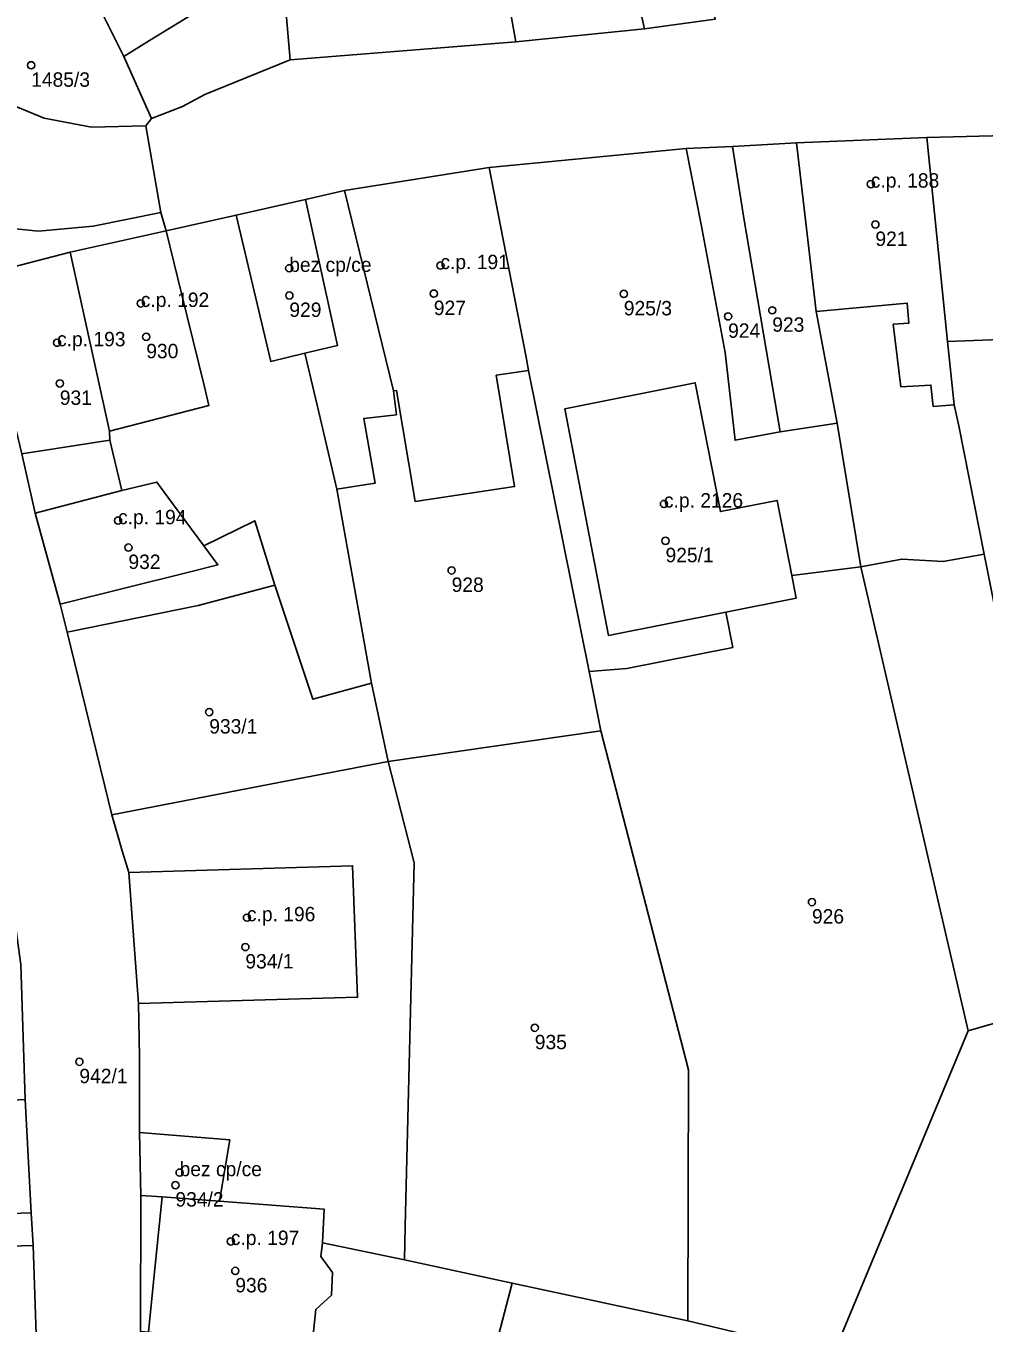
# Model space of a CAD drawing. Extents: x -878211 to -870363, y -1058464 to -1052522.
# Drawn here: x -874825.1 to -874758.5, y -1056399.5 to -1056309.4 of the extents above; entities that cross this region are included whole.
import ezdxf

# ---------------------------------------------------------------- set-up
doc = ezdxf.new("R2010")
doc.units = 0
for name, color, linetype in [('Vrstva 50', 7, 'Continuous'), ('Vrstva 51', 7, 'Continuous'), ('Vrstva 52', 7, 'Continuous')]:
    doc.layers.add(name, color=color, linetype=linetype)

msp = doc.modelspace()

# ---------------------------------------------------------------- linework, layer by layer
at = {"layer": 'Vrstva 50'}
for centre in [(-874824.76, -1056312.13994), (-874766.39, -1056320.38994), (-874766.07, -1056323.19994), (-874796.31, -1056326.04994), (-874806.82, -1056326.23994), (-874817.14, -1056328.67994), (-874806.81, -1056328.12994), (-874796.77, -1056327.99994), (-874783.56, -1056328.01994), (-874776.31, -1056329.57994), (-874773.24, -1056329.15994), (-874822.96, -1056331.40994), (-874816.76, -1056330.99994), (-874822.77, -1056334.23994), (-874780.77, -1056342.60994), (-874818.72, -1056343.76994), (-874818, -1056345.63994), (-874780.66, -1056345.16994), (-874795.53, -1056347.22994), (-874812.38, -1056357.06994), (-874770.48, -1056370.26994), (-874809.76, -1056371.34994), (-874809.87, -1056373.38994), (-874789.75, -1056378.99994), (-874821.41, -1056381.35994), (-874814.44, -1056389.05994), (-874814.73, -1056389.92994), (-874810.88, -1056393.83994), (-874810.57, -1056395.88994)]:
    msp.add_circle(centre, 0.25, dxfattribs=at)
at = {"layer": 'Vrstva 51'}
for points in [[(-874810.41, -1056299.08), (-874807.36, -1056304.78), (-874806.75, -1056311.76), (-874791.06, -1056310.51), (-874792.59, -1056302.01), (-874797.4, -1056303.06), (-874798.34, -1056300.54), (-874798.56, -1056299.76), (-874803.04, -1056301.63), (-874806.58, -1056293.34), (-874807.36, -1056291.06), (-874799.65, -1056288.2), (-874799.18, -1056288.03), (-874800.65, -1056284.47), (-874802.95, -1056281.49), (-874812.35, -1056267.76), (-874825.07, -1056277.66), (-874817.87, -1056288.24), (-874815.27, -1056292.06)], [(-874782.12, -1056309.61), (-874777.22, -1056308.94), (-874777.94, -1056303.47), (-874774.36, -1056303.02), (-874774.94, -1056298.49), (-874775.56, -1056294.88), (-874776.96, -1056286.51), (-874783.86, -1056275.07), (-874788.26, -1056278.25), (-874786.97, -1056279.79), (-874784.95, -1056283.66), (-874785.11, -1056283.85), (-874790.97, -1056286.39), (-874787.35, -1056293.96), (-874784.26, -1056300.23)], [(-874821.24, -1056305.68), (-874820.95, -1056305.48), (-874821.05, -1056305.31), (-874824.38, -1056307.31), (-874825.52, -1056305.39), (-874829.14, -1056307.57), (-874832.24, -1056302.43), (-874825.01, -1056298.2), (-874829.97, -1056300.5), (-874833.03, -1056296.06), (-874834.18, -1056296.79), (-874832.6, -1056300.12), (-874836.12, -1056302.52), (-874835.92, -1056303.06), (-874834.95, -1056305.06), (-874836.72, -1056305.96), (-874834.67, -1056309.32), (-874832.56, -1056311.43), (-874829.27, -1056313.6), (-874823.85, -1056315.82), (-874820.56, -1056316.43), (-874816.79, -1056316.35), (-874816.4, -1056315.83), (-874818.31, -1056311.52)], [(-874810.41, -1056299.08), (-874820.95, -1056305.48), (-874821.24, -1056305.68), (-874818.31, -1056311.52), (-874816.4, -1056315.83), (-874814.25, -1056315), (-874812.69, -1056314.16), (-874806.75, -1056311.76), (-874807.36, -1056304.78)], [(-874791.06, -1056310.51), (-874782.12, -1056309.61), (-874784.26, -1056300.23), (-874792.59, -1056302.01)], [(-874757.27, -1056352.27), (-874748.07, -1056351.04), (-874748.8, -1056346.87), (-874750.14, -1056339.33), (-874751.05, -1056334.17), (-874751.31, -1056330.95), (-874751.33, -1056330.7), (-874751.64, -1056326.89), (-874752.45, -1056316.91), (-874762.49, -1056317.15), (-874761.05, -1056331.33), (-874760.6, -1056335.72), (-874760.27, -1056337.19), (-874758.52, -1056346.1)], [(-874775.83, -1056338.18), (-874772.68, -1056337.6), (-874775.22, -1056322.75), (-874776, -1056317.78), (-874779.23, -1056317.93), (-874778.18, -1056323.19), (-874776.51, -1056332.1)], [(-874771.55, -1056317.53), (-874776, -1056317.78), (-874775.22, -1056322.75), (-874772.68, -1056337.6), (-874768.72, -1056336.99), (-874770.18, -1056329.24), (-874770.97, -1056322.47)], [(-874768.72, -1056336.99), (-874767.09, -1056346.97), (-874764.24, -1056346.44), (-874761.36, -1056346.61), (-874758.52, -1056346.1), (-874760.27, -1056337.19), (-874760.6, -1056335.72), (-874761.05, -1056331.33), (-874762.49, -1056317.15), (-874771.55, -1056317.53), (-874770.97, -1056322.47), (-874770.18, -1056329.24)], [(-874767.09, -1056346.97), (-874768.72, -1056336.99), (-874772.68, -1056337.6), (-874775.83, -1056338.18), (-874776.51, -1056332.1), (-874778.18, -1056323.19), (-874779.23, -1056317.93), (-874792.93, -1056319.24), (-874792.14, -1056323.29), (-874790.36, -1056332.41), (-874790.18, -1056333.33), (-874785.98, -1056354.25), (-874783.34, -1056354.04), (-874775.99, -1056352.58), (-874776.47, -1056350.13), (-874784.62, -1056351.75), (-874787.65, -1056336), (-874778.59, -1056334.19), (-874776.84, -1056343.14), (-874772.91, -1056342.37), (-874771.88, -1056347.58)], [(-874799.37, -1056334.73), (-874798.07, -1056342.44), (-874791.15, -1056341.41), (-874792.43, -1056333.67), (-874790.18, -1056333.33), (-874790.36, -1056332.41), (-874792.14, -1056323.29), (-874792.93, -1056319.24), (-874802.97, -1056320.84), (-874805.69, -1056321.47), (-874803.46, -1056331.6), (-874805.73, -1056332.14), (-874804.67, -1056336.64), (-874803.5, -1056341.58), (-874800.84, -1056341.16), (-874801.64, -1056336.67), (-874799.37, -1056336.41), (-874799.57, -1056334.76)], [(-874805.73, -1056332.14), (-874803.46, -1056331.6), (-874805.69, -1056321.47), (-874810.52, -1056322.54), (-874808.11, -1056332.71)], [(-874805.73, -1056332.14), (-874808.11, -1056332.71), (-874810.52, -1056322.54), (-874815.38, -1056323.63), (-874822.04, -1056325.11), (-874819.32, -1056337.55), (-874819.29, -1056338.18), (-874818.46, -1056341.67), (-874816.02, -1056341.09), (-874815.25, -1056342.14), (-874812.76, -1056345.51), (-874809.22, -1056343.78), (-874807.81, -1056348.25), (-874805.17, -1056356.18), (-874801.09, -1056355.05), (-874803.5, -1056341.58), (-874804.67, -1056336.64)], [(-874818.46, -1056341.67), (-874819.29, -1056338.18), (-874819.32, -1056337.55), (-874822.04, -1056325.11), (-874828.39, -1056326.76), (-874825.4, -1056339.14), (-874824.48, -1056343.25)], [(-874785.16, -1056358.37), (-874785.98, -1056354.25), (-874790.18, -1056333.33), (-874792.43, -1056333.67), (-874791.15, -1056341.41), (-874798.07, -1056342.44), (-874799.37, -1056334.73), (-874799.57, -1056334.76), (-874799.37, -1056336.41), (-874801.64, -1056336.67), (-874800.84, -1056341.16), (-874803.5, -1056341.58), (-874801.09, -1056355.05), (-874799.95, -1056360.5)], [(-874771.88, -1056347.58), (-874772.91, -1056342.37), (-874776.84, -1056343.14), (-874778.59, -1056334.19), (-874787.65, -1056336), (-874784.62, -1056351.75), (-874776.47, -1056350.13), (-874771.57, -1056349.15)], [(-874813.16, -1056349.67), (-874807.81, -1056348.25), (-874809.22, -1056343.78), (-874812.76, -1056345.51), (-874815.25, -1056342.14), (-874816.02, -1056341.09), (-874818.46, -1056341.67), (-874824.48, -1056343.25), (-874822.74, -1056349.57), (-874822.26, -1056351.51)], [(-874759.61, -1056379.22), (-874752.26, -1056377.07), (-874757.27, -1056352.27), (-874758.52, -1056346.1), (-874761.36, -1056346.61), (-874764.24, -1056346.44), (-874767.09, -1056346.97)], [(-874771.88, -1056347.58), (-874771.57, -1056349.15), (-874776.47, -1056350.13), (-874775.99, -1056352.58), (-874783.34, -1056354.04), (-874785.98, -1056354.25), (-874785.16, -1056358.37), (-874779.06, -1056381.92), (-874779.1, -1056399.35), (-874769.04, -1056401.77), (-874759.61, -1056379.22), (-874767.09, -1056346.97)], [(-874807.42, -1056361.94), (-874799.95, -1056360.5), (-874801.09, -1056355.05), (-874805.17, -1056356.18), (-874807.81, -1056348.25), (-874813.16, -1056349.67), (-874822.26, -1056351.51), (-874819.16, -1056364.21)], [(-874791.32, -1056396.73), (-874779.1, -1056399.35), (-874779.06, -1056381.92), (-874785.16, -1056358.37), (-874799.95, -1056360.5), (-874798.14, -1056367.54), (-874798.75, -1056392.78), (-874798.8, -1056395.13)], [(-874810.96, -1056386.79), (-874811.67, -1056391.05), (-874804.39, -1056391.6), (-874804.5, -1056393.93), (-874798.8, -1056395.13), (-874798.75, -1056392.78), (-874798.14, -1056367.54), (-874799.95, -1056360.5), (-874807.42, -1056361.94), (-874819.16, -1056364.21), (-874818.43, -1056366.7), (-874817.98, -1056368.21), (-874817.3, -1056377.31), (-874817.23, -1056381), (-874817.23, -1056386.28)], [(-874676.37, -1056404.7), (-874677.01, -1056392.06), (-874685.65, -1056392.4), (-874695.66, -1056392.71), (-874699.02, -1056385.96), (-874705.69, -1056372.77), (-874709.26, -1056366.25), (-874719.04, -1056368.48), (-874720.98, -1056368.98), (-874735.34, -1056372.63), (-874743.87, -1056374.83), (-874752.26, -1056377.07), (-874759.61, -1056379.22), (-874769.04, -1056401.77), (-874773.98, -1056413.47), (-874779.49, -1056427.06), (-874780.55, -1056429.67), (-874762.07, -1056437.23), (-874747.48, -1056443.08), (-874718.21, -1056454.5), (-874706.91, -1056430.53), (-874696.83, -1056406.55), (-874687.37, -1056405.45), (-874685.09, -1056405.18)], [(-874837.74, -1056384.7), (-874843.27, -1056385), (-874850.58, -1056385.39), (-874850.27, -1056392.72), (-874824.76, -1056391.85), (-874825.18, -1056383.98), (-874835.24, -1056384.52)], [(-874815.66, -1056390.75), (-874811.67, -1056391.05), (-874810.96, -1056386.79), (-874817.23, -1056386.28), (-874817.14, -1056390.64)], [(-874816.61, -1056400.15), (-874810.51, -1056401.57), (-874801.88, -1056403.67), (-874793.86, -1056406.49), (-874791.32, -1056396.73), (-874798.8, -1056395.13), (-874804.5, -1056393.93), (-874804.39, -1056391.6), (-874811.67, -1056391.05), (-874815.66, -1056390.75), (-874817.14, -1056390.64), (-874817.16, -1056400.09)], [(-874862.13, -1056399.47), (-874860.57, -1056399.52), (-874853.61, -1056399.99), (-874845.68, -1056401.18), (-874841.61, -1056401.26), (-874824.39, -1056400.97), (-874824.63, -1056394.12), (-874824.76, -1056391.85), (-874850.27, -1056392.72), (-874861.41, -1056393.71)], [(-874780.89, -1056411.04), (-874773.98, -1056413.47), (-874769.04, -1056401.77), (-874779.1, -1056399.35), (-874791.32, -1056396.73), (-874793.86, -1056406.49)]]:
    msp.add_lwpolyline(points, close=True, dxfattribs=at)
for points in [[(-874849.9, -1056307.62), (-874848.15, -1056310.07), (-874842.64, -1056317.17), (-874841.11, -1056319.16), (-874839.69, -1056321.22), (-874838.05, -1056324.25), (-874836.53, -1056327.36), (-874834.97, -1056330.54), (-874828.39, -1056326.76), (-874822.04, -1056325.11), (-874815.38, -1056323.63), (-874815.74, -1056322.36), (-874820.44, -1056323.31), (-874824.26, -1056323.66), (-874829.04, -1056323.18), (-874833.17, -1056321.81), (-874836.69, -1056319.95), (-874838.9, -1056318.27), (-874844.39, -1056311.78), (-874848.34, -1056306.37)], [(-874848.34, -1056306.37), (-874844.39, -1056311.78), (-874838.9, -1056318.27), (-874836.69, -1056319.95), (-874833.17, -1056321.81), (-874829.04, -1056323.18), (-874824.26, -1056323.66), (-874820.44, -1056323.31), (-874815.74, -1056322.36), (-874816.79, -1056316.35), (-874820.56, -1056316.43), (-874823.85, -1056315.82), (-874829.27, -1056313.6), (-874832.56, -1056311.43), (-874834.67, -1056309.32)], [(-874777.22, -1056308.94), (-874782.12, -1056309.61), (-874791.06, -1056310.51), (-874806.75, -1056311.76), (-874812.69, -1056314.16), (-874814.25, -1056315), (-874816.4, -1056315.83), (-874816.79, -1056316.35), (-874815.74, -1056322.36), (-874815.38, -1056323.63), (-874810.52, -1056322.54), (-874805.69, -1056321.47), (-874802.97, -1056320.84), (-874792.93, -1056319.24), (-874779.23, -1056317.93), (-874776, -1056317.78), (-874771.55, -1056317.53), (-874762.49, -1056317.15), (-874752.45, -1056316.91)], [(-874817.16, -1056400.09), (-874817.14, -1056390.64), (-874817.23, -1056386.28), (-874817.23, -1056381), (-874817.3, -1056377.31), (-874817.98, -1056368.21), (-874818.43, -1056366.7), (-874819.16, -1056364.21), (-874822.26, -1056351.51), (-874822.74, -1056349.57), (-874824.48, -1056343.25), (-874825.4, -1056339.14), (-874828.39, -1056326.76), (-874834.97, -1056330.54), (-874830.86, -1056342.24), (-874829.1, -1056348.82), (-874827.6, -1056357.18), (-874826.34, -1056367.98), (-874826.37, -1056368.2), (-874825.47, -1056374.6), (-874825.18, -1056383.98), (-874824.76, -1056391.85), (-874824.63, -1056394.12), (-874824.39, -1056400.97)]]:
    msp.add_lwpolyline(points, dxfattribs=at)
at = {"layer": 'Vrstva 52'}
for points in [[(-874821.24, -1056305.68), (-874818.31, -1056311.52), (-874816.53, -1056310.41), (-874807.36, -1056304.78), (-874810.41, -1056299.08), (-874820.95, -1056305.48)], [(-874762.49, -1056317.15), (-874761.05, -1056331.33), (-874751.31, -1056330.95), (-874751.33, -1056330.7), (-874751.64, -1056326.89), (-874752.45, -1056316.91)], [(-874771.55, -1056317.53), (-874770.97, -1056322.47), (-874770.18, -1056329.24), (-874763.87, -1056328.66), (-874763.74, -1056330.05), (-874764.84, -1056330.13), (-874764.3, -1056334.48), (-874762.21, -1056334.35), (-874762.05, -1056335.83), (-874760.6, -1056335.72), (-874761.05, -1056331.33), (-874762.49, -1056317.15)], [(-874802.97, -1056320.84), (-874799.57, -1056334.76), (-874799.37, -1056334.73), (-874798.07, -1056342.44), (-874791.15, -1056341.41), (-874792.43, -1056333.67), (-874790.18, -1056333.33), (-874790.36, -1056332.41), (-874792.14, -1056323.29), (-874792.93, -1056319.24)], [(-874810.52, -1056322.54), (-874808.11, -1056332.71), (-874805.73, -1056332.14), (-874803.46, -1056331.6), (-874805.69, -1056321.47)], [(-874822.04, -1056325.11), (-874819.32, -1056337.55), (-874812.4, -1056335.77), (-874812.72, -1056334.48), (-874814.31, -1056327.99), (-874815.38, -1056323.63)], [(-874819.32, -1056337.55), (-874822.04, -1056325.11), (-874828.39, -1056326.76), (-874825.4, -1056339.14), (-874819.29, -1056338.18)], [(-874787.65, -1056336), (-874784.62, -1056351.75), (-874776.47, -1056350.13), (-874771.57, -1056349.15), (-874771.88, -1056347.58), (-874772.91, -1056342.37), (-874776.84, -1056343.14), (-874778.59, -1056334.19)], [(-874824.48, -1056343.25), (-874822.74, -1056349.57), (-874813.79, -1056347.34), (-874811.78, -1056346.83), (-874812.76, -1056345.51), (-874815.25, -1056342.14), (-874816.02, -1056341.09), (-874818.46, -1056341.67)], [(-874817.98, -1056368.21), (-874817.3, -1056377.31), (-874802.07, -1056376.88), (-874802.42, -1056367.74)], [(-874810.96, -1056386.79), (-874817.23, -1056386.28), (-874817.14, -1056390.64), (-874815.66, -1056390.75), (-874811.67, -1056391.05)], [(-874816.61, -1056400.15), (-874810.42, -1056400.73), (-874810.51, -1056401.57), (-874805.33, -1056402.1), (-874804.98, -1056398.56), (-874803.89, -1056397.57), (-874803.81, -1056396.01), (-874804.62, -1056394.88), (-874804.5, -1056393.93), (-874804.39, -1056391.6), (-874811.67, -1056391.05), (-874815.66, -1056390.75), (-874816.23, -1056396.42)], [(-874845.83, -1056394.73), (-874845.68, -1056401.18), (-874841.61, -1056401.26), (-874824.39, -1056400.97), (-874824.63, -1056394.12)]]:
    msp.add_lwpolyline(points, close=True, dxfattribs=at)

# ---------------------------------------------------------------- texts
at = {"layer": 'Vrstva 50'}
for s, p in [('1485/3', (-874824.76, -1056313.629)), ('c.p. 188', (-874766.39, -1056320.639)), ('921', (-874766.07, -1056324.689)), ('bez cp/ce', (-874806.82, -1056326.49)), ('c.p. 191', (-874796.31, -1056326.3)), ('c.p. 192', (-874817.14, -1056328.929)), ('929', (-874806.81, -1056329.619)), ('927', (-874796.77, -1056329.489)), ('925/3', (-874783.56, -1056329.509)), ('924', (-874776.31, -1056331.069)), ('923', (-874773.24, -1056330.649)), ('c.p. 193', (-874822.96, -1056331.659)), ('930', (-874816.76, -1056332.489)), ('931', (-874822.77, -1056335.729)), ('c.p. 2126', (-874780.77, -1056342.86)), ('c.p. 194', (-874818.72, -1056344.02)), ('925/1', (-874780.66, -1056346.659)), ('932', (-874818, -1056347.129)), ('928', (-874795.53, -1056348.719)), ('933/1', (-874812.38, -1056358.559)), ('c.p. 196', (-874809.76, -1056371.6)), ('926', (-874770.48, -1056371.759)), ('934/1', (-874809.87, -1056374.879)), ('935', (-874789.75, -1056380.489)), ('942/1', (-874821.41, -1056382.849)), ('bez cp/ce', (-874814.44, -1056389.31)), ('934/2', (-874814.73, -1056391.419)), ('c.p. 197', (-874810.88, -1056394.09)), ('936', (-874810.57, -1056397.379))]:
    msp.add_text(s, height=0.999996, dxfattribs=at).set_placement(p)

doc.saveas('drawing.dxf')
